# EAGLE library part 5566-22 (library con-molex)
Mini FIT connector 22 pol Source: http://www.molex.com
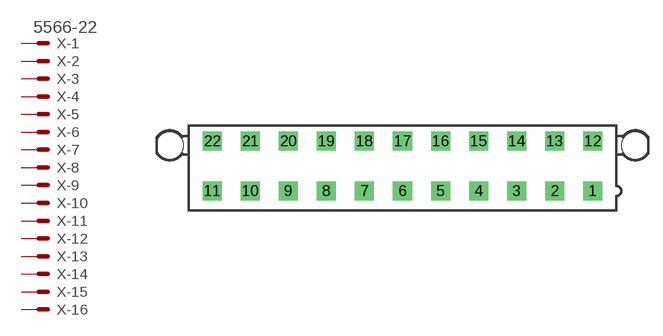
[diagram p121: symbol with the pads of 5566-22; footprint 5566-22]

Designator prefix X; gates -1=MV -2=M -3=M -4=M -5=M -6=M -7=M -8=M -9=M -10=M -11=M -12=M -13=M -14=M -15=M -16=M -17=M -18=M -19=M -20=M -21=M -22=M

## 5566-22 (OC_FARNELL: unknown; OC_NEWARK: unknown)  [5566-22]
1  -1:S  pas
2  -2:S  pas
3  -3:S  pas
4  -4:S  pas
5  -5:S  pas
6  -6:S  pas
7  -7:S  pas
8  -8:S  pas
9  -9:S  pas
10  -10:S  pas
11  -11:S  pas
12  -12:S  pas
13  -13:S  pas
14  -14:S  pas
15  -15:S  pas
16  -16:S  pas
17  -17:S  pas
18  -18:S  pas
19  -19:S  pas
20  -20:S  pas
21  -21:S  pas
22  -22:S  pas

## Footprint 5566-22 (pad centres in mm)
Mini FIT connector 22 pol Source: http://www.molex.com
drill 1.4 square: 1 21,-2.75; 2 16.8,-2.75; 3 12.6,-2.75; 4 8.4,-2.75; 5 4.2,-2.75; 6 0,-2.75; 7 -4.2,-2.75; 8 -8.4,-2.75; 9 -12.6,-2.75; 10 -16.8,-2.75; 11 -21,-2.75; 12 21,2.75; 13 16.8,2.75; 14 12.6,2.75; 15 8.4,2.75; 16 4.2,2.75; 17 0,2.75; 18 -4.2,2.75; 19 -8.4,2.75; 20 -12.6,2.75; 21 -16.8,2.75; 22 -21,2.75
hole 3 at 25.7,2.29
hole 3 at -25.7,2.29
